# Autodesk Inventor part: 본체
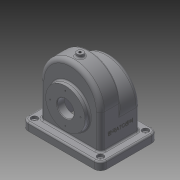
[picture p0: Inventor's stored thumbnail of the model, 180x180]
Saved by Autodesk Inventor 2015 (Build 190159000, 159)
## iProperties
Created: 2017-11
Part Number: 본체
Material: 일반
Document SubType Name: Modeling
Designer: 2-PC10
Density: 1 g/cm^3
Appearance: 기본값
Author: 2-PC10
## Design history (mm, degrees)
sketch "스케치1"
  geometry: L1 (-75, 55)-(75, 55); L2 (75, 55)-(75, -55); L3 (75, -55)-(-75, -55); L4 (-75, -55)-(-75, 55); L5 (-75, 55)-(75, -55); L6 (75, 55)-(-75, -55); 1 further point
  constraints: 12 end point, 2 midpoint, 2 parallel, 1 horizontal, 1 perpendicular
  dimensions: "d0" = 110 distance between parallel lines of L3 L1; "d1" = 150 distance between parallel lines of L2 L4
extrude "돌출1" new body sketch "스케치1" distance "d2" = 15; taper "d3" = 0 deg
sketch "스케치2"
  geometry: L1 (58, 80)-(58, 15); L2 (-58, 80)-(-58, 15); L3 (-75, 15)-(75, 15) reference; L4 (75, 0)-(-75, 0) reference; A1 r 58 centre (0, 80) between (-58, 80) and (58, 80); 1 further point
  constraints: 4 end point, 2 point on circle, 2 point on line, 2 tangent, 2 vertical, 1 centre point, 1 vertical alignment
  dimensions: "d5" = 58 radius of A1; "d6" = 80 distance from line of L4 A1.centre
extrude "돌출2" join sketch "스케치2" stored distance "d7" = 76; taper "d8" = 0 deg
sketch "스케치3"
  geometry: L1 (75, 0)-(-75, 0) reference; C1 r 37.5 at (0, 65); 2 further points
  constraints: 1 centre point, 1 midpoint, 1 vertical alignment
  dimensions: "d9" = 75 diameter of C1; "d10" = 65 distance from line of L1 C1.centre
extrude "돌출3" join sketch "스케치3" distance "d11" = 9; taper "d12" = 0 deg
sketch "스케치4"
  geometry: L1 (-75, 0)-(75, 0) reference; C1 r 31 at (0, -65); 2 further points
  constraints: 1 centre point, 1 midpoint, 1 vertical alignment
  dimensions: "d13" = 62 diameter of C1; "d14" = 65 distance from line of L1 C1.centre
extrude "돌출4" join sketch "스케치4" distance "d15" = 10; taper "d16" = 0 deg
sketch "스케치5"
  geometry: L1 (75, 0)-(-75, 0) reference; L2 (58, -15)-(58, -80) reference; L3 (-58, -80)-(-58, -15) reference; A1 r 58 centre (0, -57) between (-58, -57) and (58, -57); A2 r 58 centre (0, -80) between (-58, -80) and (58, -80) reference; 1 further point
  constraints: 2 point on circle, 2 point on line, 1 centre point, 1 midpoint, 1 vertical alignment
  dimensions: "d22" = 58 radius of A1; "d23" = 57 distance from line of L1 A1.centre
extrude "돌출5" cut sketch "스케치5" distance "d24" = 38; taper "d25" = 0 deg
sketch "스케치6"
  geometry: L1 (-53, -33)-(53, -33); L2 (53, -33)-(53, 33); L3 (53, 33)-(-53, 33); L4 (-53, 33)-(-53, -33); L5 (-53, -33)-(53, 33); L6 (53, -33)-(-53, 33); 1 further point
  constraints: 12 end point, 2 midpoint, 2 parallel, 1 horizontal, 1 perpendicular
  dimensions: "d26" = 66 distance between parallel lines of L3 L1; "d27" = 106 distance between parallel lines of L2 L4
extrude "돌출6" cut sketch "스케치6" distance "d28" = 15; taper "d29" = 0 deg
hole "구멍1" diameter "d33" = 32; stored, may be unused: countersink angle "d37" = 90 deg, drill point angle "d39" = 118 deg; dims "d31" = 10, "d32" = 10, "d34" = 6, "d35" = 4, "d36" = 2, "d38" = 8
node "작업 평면2"
sketch "스케치8"
  geometry: L1 (-53, -15)-(53, -15) reference; L2 (53, -57)-(53, -15); L3 (-53, -57)-(-53, -15); A1 r 58 centre (0, -57) between (-58, -57) and (58, -57) reference; A2 r 53 centre (0, -57) between (-53, -57) and (53, -57); 1 further point
  constraints: 4 end point, 2 perpendicular, 2 point on circle, 1 centre point, 1 coincident
  dimensions: "d43" = 53 radius of A2
extrude "돌출7" cut sketch "스케치8" distance "d44" = 40; taper "d45" = 0 deg
node "작업 평면3"
sketch "스케치9"
  geometry: L1 (53, -80)-(53, -15); L2 (-53, -80)-(-53, -15); L3 (53, -15)-(-53, -15); A1 r 53 centre (0, -80) between (-53, -80) and (53, -80); 1 further point
  constraints: 6 end point, 2 point on circle, 2 vertical, 1 centre point, 1 horizontal, 1 tangent
  dimensions: "d47" = 53 radius of A1; "d48" = 80 distance of point (0, 0) A1.centre
extrude "돌출8" cut sketch "스케치9" distance "d49" = 28; taper "d50" = 0 deg
sketch "스케치10"
  geometry: C1 r 37.5 at (0, 0) reference; A1 r 29 centre (0, 0) between (0, 29) and (-29, 0); 3 further points
  constraints: 4 point on circle, 2 horizontal alignment, 2 vertical alignment, 1 centre point, 1 coincident
  dimensions: "d51" = 58 diameter of A1
hole "구멍2" sketch "스케치10" at (0, 29), (-29, 0), (0, -29), (29, 0) diameter "d52" = 2.459; stored, may be unused: countersink angle "d56" = 90 deg, drill point angle "d58" = 118 deg; dims "d53" = 6, "d54" = 4, "d55" = 2, "d57" = 8
sketch "스케치11"
  geometry: C1 r 31 at (0, 0) reference; A1 r 26 centre (0, 0) between (0, -26) and (26, 0); 3 further points
  constraints: 4 point on circle, 2 horizontal alignment, 2 vertical alignment, 1 centre point, 1 coincident
  dimensions: "d59" = 52 diameter of A1
hole "구멍3" sketch "스케치11" at (0, -26), (26, 0), (0, 26), (-26, 0) diameter "d60" = 2.459; stored, may be unused: countersink angle "d64" = 90 deg, drill point angle "d66" = 118 deg; dims "d61" = 6, "d62" = 4, "d63" = 2, "d65" = 8
node "작업 평면4"
sketch "스케치13"
  geometry: L1 (-58, -38)-(58, -38) reference; C1 r 6 at (0, -19); 1 further point
  constraints: 1 centre point, 1 vertical alignment
  dimensions: "d68" = 12 diameter of C1; "d69" = 19 distance from line of L1 C1.centre
extrude "돌출9" join sketch "스케치13" stored distance "d70" = 28; taper "d71" = 0 deg
fillet "모깎기1" dims "d72" = 12
hole "구멍4" diameter "d75" = 12; stored, may be unused: countersink angle "d79" = 90 deg, drill point angle "d81" = 0 deg; dims "d73" = 10, "d74" = 10, "d76" = 6, "d77" = 4, "d78" = 2, "d80" = 5
hole "구멍5" diameter "d84" = 12; stored, may be unused: countersink angle "d88" = 90 deg, drill point angle "d90" = 0 deg; dims "d82" = 10, "d83" = 10, "d85" = 6, "d86" = 4, "d87" = 2, "d89" = 5
hole "구멍6" diameter "d93" = 12; stored, may be unused: countersink angle "d97" = 90 deg, drill point angle "d99" = 0 deg; dims "d91" = 10, "d92" = 10, "d94" = 6, "d95" = 4, "d96" = 2, "d98" = 5
hole "구멍7" diameter "d102" = 12; stored, may be unused: countersink angle "d106" = 90 deg, drill point angle "d108" = 0 deg; dims "d100" = 10, "d101" = 10, "d103" = 6, "d104" = 4, "d105" = 2, "d107" = 5
hole "구멍8" diameter "d111" = 5; stored, may be unused: countersink angle "d115" = 90 deg, drill point angle "d117" = 0 deg; dims "d109" = 10, "d110" = 10, "d112" = 6, "d113" = 4, "d114" = 2, "d116" = 5
hole "구멍9" diameter "d120" = 5; stored, may be unused: countersink angle "d124" = 90 deg, drill point angle "d126" = 0 deg; dims "d118" = 10, "d119" = 10, "d121" = 6, "d122" = 4, "d123" = 2, "d125" = 5
hole "구멍10" diameter "d129" = 5; stored, may be unused: countersink angle "d133" = 90 deg, drill point angle "d135" = 0 deg; dims "d127" = 10, "d128" = 10, "d130" = 6, "d131" = 4, "d132" = 2, "d134" = 5
hole "구멍11" diameter "d138" = 5; stored, may be unused: countersink angle "d142" = 90 deg, drill point angle "d144" = 0 deg; dims "d136" = 10, "d137" = 10, "d139" = 6, "d140" = 4, "d141" = 2, "d143" = 5
chamfer "모따기1" distance "d145" = 1; stored, may be unused: second distance "d146" = 2, angle "d147" = 45 deg
fillet "모깎기2" dims "d148" = 3
hole "구멍12" diameter "d151" = 4.459; stored, may be unused: countersink angle "d155" = 90 deg, drill point angle "d157" = 118 deg; dims "d149" = 10, "d150" = 10, "d152" = 10, "d153" = 4, "d154" = 2, "d156" = 12.8
sketch "스케치14"
  geometry: L1 (-31.5, 13)-(-31.5, 63); L2 (-31.5, 63)-(-18.5, 63); L3 (-18.5, 63)-(-18.5, 13); L4 (-18.5, 13)-(-31.5, 13); L5 (-31.5, 38)-(-18.5, 38); L6 (-25, 63)-(-25, 13); L7 (0, 0)-(-65, 0) reference; L8 (15, 81)-(15, -5) reference; 1 further point
  constraints: 4 end point, 4 midpoint, 2 other
  dimensions: "d158" = 13 distance between parallel lines of L3 L1; "d159" = 50 distance between parallel lines of L4 L2; "d160" = 38 distance between parallel lines of L7 L5; "d161" = 40 distance between parallel lines of L8 L6
feature "엠보싱1" sketch "스케치14" dims "d9" = 75, "d10" = 65, "d162" = 0.5, "d163" = 0
fillet "모깎기4" dims "d165" = 8
fillet "모깎기5" dims "d166" = 3
node "솔리드1"
other parameters: "d20" = 58, "d41" = -5, "d46" = -5, "d67" = 144
